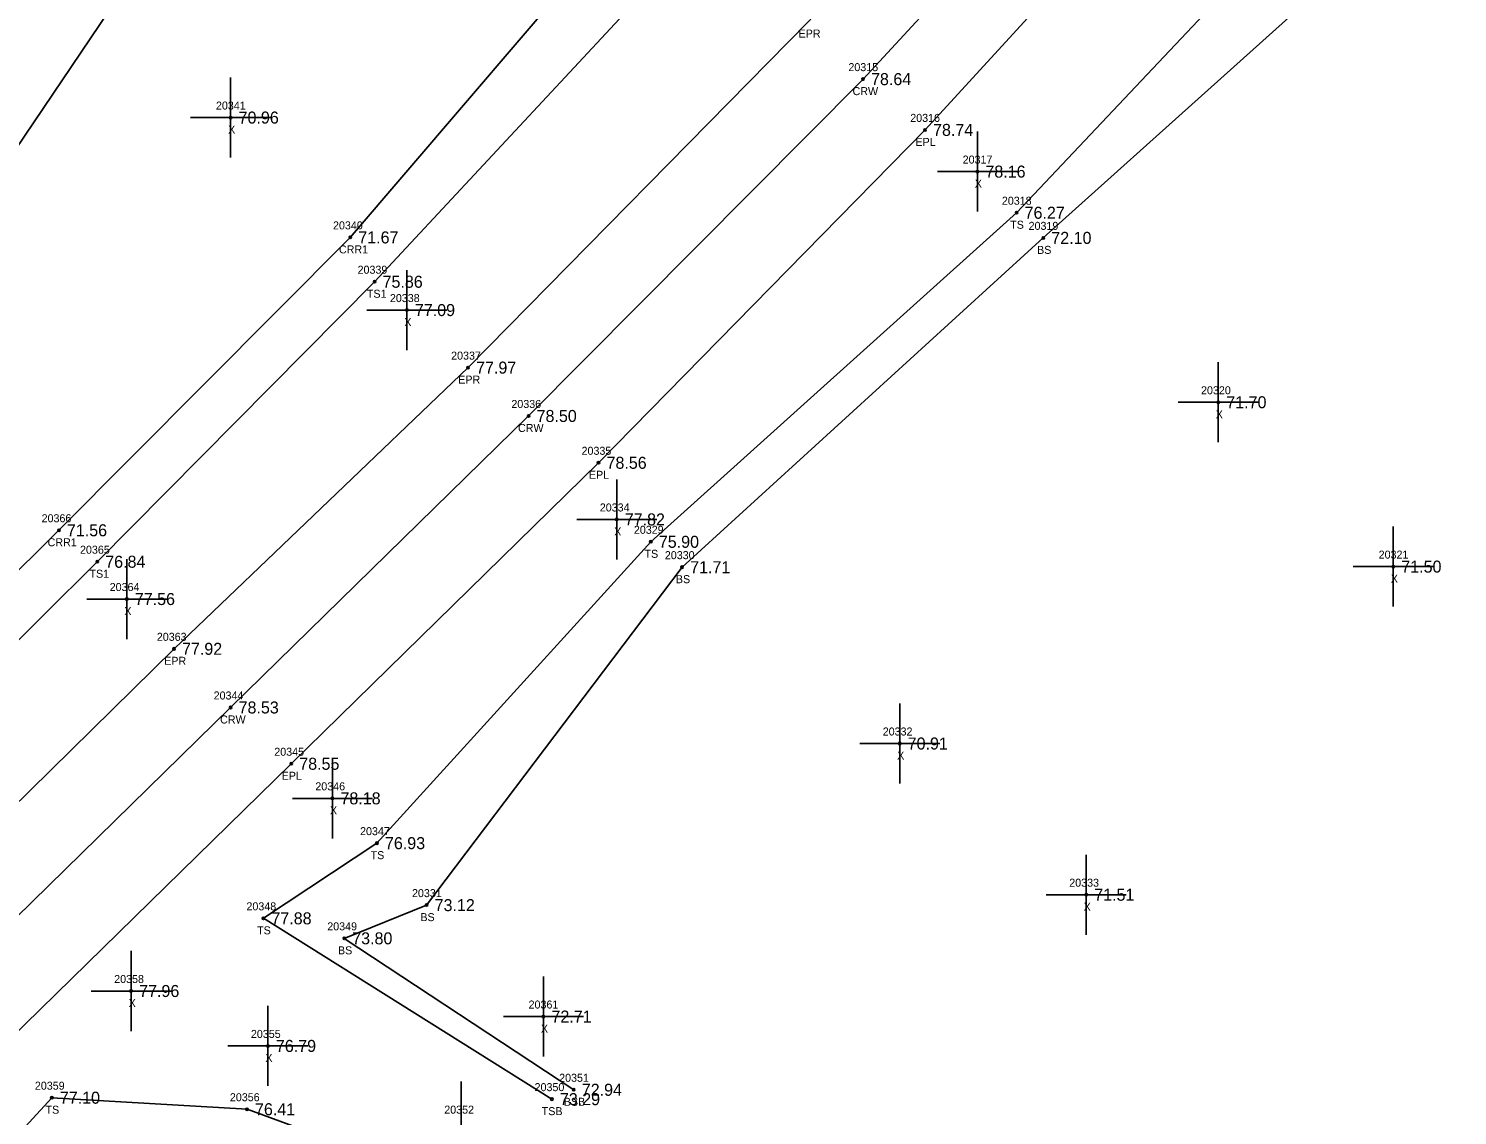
# Model space of a CAD drawing. Extents: x 2505300 to 2506184, y 912965 to 913825.
# Drawn here: x 2505552.8 to 2505731.4, y 913206.7 to 913342.5 of the extents above; entities that cross this region are included whole.
import ezdxf

# ---------------------------------------------------------------- set-up
doc = ezdxf.new("R2010")
doc.units = 0
for name, color, linetype in [('RD_DTM_BkLn1', 7, 'Continuous'), ('RD_DTM_BkLn2', 7, 'Continuous'), ('RD_DTM_BkLn_txCode', 7, 'Continuous'), ('RD_EX_H2O', 7, 'Continuous'), ('RD_EX_H2O_txCode', 7, 'Continuous'), ('RD_EX_Misc', 7, 'Continuous'), ('RD_EX_Misc_txCode', 7, 'Continuous'), ('RD_EX_Road', 7, 'Continuous'), ('RD_EX_Road_txCode', 7, 'Continuous'), ('RD_EX_TX_H2O_ELEV', 7, 'Continuous'), ('RD_EX_TX_Misc_ELEV', 7, 'Continuous'), ('RD_EX_TX_Road_ELEV', 7, 'Continuous'), ('RD_HC_Survey_ELEV', 7, 'Continuous'), ('RD_HC_Survey_txCode', 7, 'Continuous'), ('RD_SMD_Locator', 7, 'Continuous')]:
    doc.layers.add(name, color=color, linetype=linetype)

msp = doc.modelspace()

# ---------------------------------------------------------------- linework, layer by layer
at = {"layer": 'RD_DTM_BkLn1'}
msp.add_lwpolyline([(2505767.92, 913463.52), (2505733.49, 913421.6), (2505698.21, 913380.67), (2505657.08, 913336.16), (2505615.28, 913294.08), (2505578.04, 913257.66), (2505509.81, 913190.87), (2505437.56, 913120.73), (2505363.23, 913048.54)], dxfattribs=at)
at = {"layer": 'RD_DTM_BkLn2'}
for points in [[(2505753.71, 913473.94), (2505744.94, 913478.08), (2505723.86, 913460.1), (2505705.31, 913435.28), (2505675.97, 913399.31), (2505635.15, 913352.85), (2505596.03, 913310.85), (2505561.37, 913275.87), (2505492.57, 913207.56), (2505417.69, 913144.74), (2505344.31, 913068.67)], [(2505795.69, 913463.1), (2505792.51, 913445.22), (2505759.98, 913398.97), (2505723.99, 913356.17), (2505679.61, 913316.33), (2505634.47, 913275.19), (2505602.54, 913232.97), (2505592.24, 913228.82), (2505620.93, 913209.9)], [(2505778.84, 913452.68), (2505749.61, 913407.4), (2505717.38, 913363.03), (2505676.27, 913319.47), (2505630.56, 913278.36), (2505596.33, 913240.71), (2505582.14, 913231.32), (2505618.19, 913208.73)], [(2505608.57, 913197.02), (2505580.09, 913207.47), (2505555.7, 913208.91), (2505524.48, 913174.98), (2505452.19, 913104.88), (2505378.2, 913033.83)]]:
    msp.add_lwpolyline(points, dxfattribs=at)
at = {"layer": 'RD_EX_H2O'}
for points in [[(2505789.47, 913464.31), (2505758.18, 913486.1), (2505736.66, 913480.49), (2505719.32, 913463.86), (2505699.9, 913439.21), (2505669.03, 913402.75), (2505628.5, 913357.9), (2505593, 913316.39), (2505556.58, 913279.8), (2505487.72, 913211.38), (2505413.81, 913149.81), (2505341.31, 913072.1)], [(2505660.9, 913411.21), (2505598.96, 913382.03), (2505565.24, 913348.29), (2505539.28, 913309.84), (2505469.64, 913225.59)]]:
    msp.add_lwpolyline(points, dxfattribs=at)
at = {"layer": 'RD_EX_Misc'}
for p, q in [((2505578.04, 913326.36), (2505578.04, 913336.36)), ((2505573.04, 913331.36), (2505583.04, 913331.36)), ((2505671.37, 913319.61), (2505671.37, 913329.61)), ((2505666.37, 913324.61), (2505676.37, 913324.61)), ((2505600.07, 913302.31), (2505600.07, 913312.31)), ((2505595.07, 913307.31), (2505605.07, 913307.31)), ((2505701.48, 913290.79), (2505701.48, 913300.79)), ((2505696.48, 913295.79), (2505706.48, 913295.79)), ((2505626.3, 913276.15), (2505626.3, 913286.15)), ((2505621.3, 913281.15), (2505631.3, 913281.15)), ((2505723.35, 913270.26), (2505723.35, 913280.26)), ((2505565.07, 913266.21), (2505565.07, 913276.21)), ((2505718.35, 913275.26), (2505728.35, 913275.26)), ((2505560.07, 913271.21), (2505570.07, 913271.21)), ((2505661.66, 913248.16), (2505661.66, 913258.16)), ((2505656.66, 913253.16), (2505666.66, 913253.16)), ((2505590.77, 913241.31), (2505590.77, 913251.31)), ((2505585.77, 913246.31), (2505595.77, 913246.31)), ((2505684.97, 913229.27), (2505684.97, 913239.27)), ((2505679.97, 913234.27), (2505689.97, 913234.27)), ((2505565.61, 913217.24), (2505565.61, 913227.24)), ((2505617.14, 913214.05), (2505617.14, 913224.05)), ((2505560.61, 913222.24), (2505570.61, 913222.24)), ((2505582.7, 913210.38), (2505582.7, 913220.38)), ((2505612.14, 913219.05), (2505622.14, 913219.05)), ((2505577.7, 913215.38), (2505587.7, 913215.38)), ((2505606.85, 913200.92), (2505606.85, 913210.92))]:
    msp.add_line(p, q, dxfattribs=at)
at = {"layer": 'RD_EX_Road'}
for points in [[(2505758.23, 913470.96), (2505754.11, 913462.85), (2505725.4, 913427.85), (2505690.77, 913387.11), (2505650.25, 913343.36), (2505607.72, 913300.12), (2505570.97, 913264.99), (2505501.53, 913196.72), (2505431.76, 913128.83), (2505356.25, 913055.37)], [(2505777.56, 913455.88), (2505770.31, 913449.85), (2505741, 913414.45), (2505705.55, 913374.27), (2505664.83, 913329.82), (2505624.02, 913288.23), (2505585.62, 913250.63), (2505516.95, 913183.5), (2505444.27, 913113.56), (2505370.6, 913041.78)]]:
    msp.add_lwpolyline(points, dxfattribs=at)
at = {"layer": 'RD_SMD_Locator'}
for centre in [(2505657.08, 913336.16), (2505578.04, 913331.36), (2505664.83, 913329.82), (2505671.37, 913324.61), (2505676.27, 913319.47), (2505593, 913316.39), (2505679.61, 913316.33), (2505596.03, 913310.85), (2505600.07, 913307.31), (2505607.72, 913300.12), (2505701.48, 913295.79), (2505615.28, 913294.08), (2505624.02, 913288.23), (2505626.3, 913281.15), (2505556.58, 913279.8), (2505630.56, 913278.36), (2505561.37, 913275.87), (2505634.47, 913275.19), (2505723.35, 913275.26), (2505565.07, 913271.21), (2505570.97, 913264.99), (2505578.04, 913257.66), (2505661.66, 913253.16), (2505585.62, 913250.63), (2505590.77, 913246.31), (2505596.33, 913240.71), (2505602.54, 913232.97), (2505684.97, 913234.27), (2505582.14, 913231.32), (2505592.24, 913228.82), (2505565.61, 913222.24), (2505617.14, 913219.05), (2505582.7, 913215.38), (2505620.93, 913209.9), (2505555.7, 913208.91), (2505618.19, 913208.73), (2505580.09, 913207.47)]:
    msp.add_circle(centre, 0.15, dxfattribs=at)

# ---------------------------------------------------------------- texts
at = {"layer": 'RD_DTM_BkLn_txCode'}
for s, p in [('20318', (2505674.43, 913320.47)), ('TS', (2505675.47, 913317.47)), ('20319', (2505677.77, 913317.33)), ('BS', (2505678.83, 913314.33)), ('20339', (2505593.91, 913311.85)), ('TS1', (2505595.07, 913308.85)), ('20329', (2505628.44, 913279.36)), ('20365', (2505559.22, 913276.87)), ('TS', (2505629.77, 913276.36)), ('20330', (2505632.31, 913276.19)), ('TS1', (2505560.4, 913273.87)), ('BS', (2505633.69, 913273.19)), ('20347', (2505594.22, 913241.71)), ('TS', (2505595.54, 913238.71)), ('20331', (2505600.71, 913233.97)), ('20348', (2505580.02, 913232.32)), ('BS', (2505601.76, 913230.97)), ('TS', (2505581.35, 913229.32)), ('20349', (2505590.12, 913229.82)), ('BS', (2505591.46, 913226.82)), ('20351', (2505619.1, 913210.9)), ('20359', (2505553.58, 913209.91)), ('20350', (2505616.03, 913209.73)), ('20356', (2505577.95, 913208.47)), ('BSB', (2505619.68, 913207.9)), ('TS', (2505554.91, 913206.91)), ('TSB', (2505616.92, 913206.73))]:
    msp.add_text(s, height=1, dxfattribs=at).set_placement(p)
at = {"layer": 'RD_EX_H2O_txCode'}
for s, p in [('20340', (2505590.84, 913317.39)), ('CRR1', (2505591.58, 913314.39)), ('20366', (2505554.42, 913280.8)), ('CRR1', (2505555.17, 913277.8))]:
    msp.add_text(s, height=1, dxfattribs=at).set_placement(p)
at = {"layer": 'RD_EX_Misc_txCode'}
for s, p in [('20341', (2505576.21, 913332.36)), ('X', (2505577.73, 913329.36)), ('20317', (2505669.53, 913325.61)), ('X', (2505671.05, 913322.61)), ('20338', (2505597.95, 913308.31)), ('X', (2505599.75, 913305.31)), ('20320', (2505699.32, 913296.79)), ('X', (2505701.16, 913293.79)), ('20334', (2505624.18, 913282.15)), ('X', (2505625.98, 913279.15)), ('20321', (2505721.52, 913276.26)), ('X', (2505723.04, 913273.26)), ('20364', (2505562.93, 913272.21)), ('X', (2505564.76, 913269.21)), ('20332', (2505659.54, 913254.16)), ('X', (2505661.35, 913251.16)), ('20346', (2505588.63, 913247.31)), ('X', (2505590.46, 913244.31)), ('20333', (2505682.85, 913235.27)), ('X', (2505684.65, 913232.27)), ('20358', (2505563.49, 913223.24)), ('X', (2505565.3, 913220.24)), ('20361', (2505615.28, 913220.05)), ('20355', (2505580.58, 913216.38)), ('X', (2505616.82, 913217.05)), ('X', (2505582.38, 913213.38)), ('20352', (2505604.74, 913206.92))]:
    msp.add_text(s, height=1, dxfattribs=at).set_placement(p)
at = {"layer": 'RD_EX_Road_txCode'}
for s, p in [('EPR', (2505649.02, 913341.36)), ('20316', (2505662.98, 913330.82)), ('EPL', (2505663.63, 913327.82)), ('20337', (2505605.6, 913301.12)), ('EPR', (2505606.49, 913298.12)), ('20335', (2505621.9, 913289.23)), ('EPL', (2505622.82, 913286.23)), ('20363', (2505568.82, 913265.99)), ('EPR', (2505569.74, 913262.99)), ('20345', (2505583.5, 913251.63)), ('EPL', (2505584.42, 913248.63))]:
    msp.add_text(s, height=1, dxfattribs=at).set_placement(p)
at = {"layer": 'RD_EX_TX_H2O_ELEV'}
for s, p in [('71.67', (2505594, 913315.64)), ('71.56', (2505557.58, 913279.05))]:
    msp.add_text(s, height=1.5, dxfattribs=at).set_placement(p)
at = {"layer": 'RD_EX_TX_Misc_ELEV'}
for s, p in [('70.96', (2505579.04, 913330.61)), ('78.16', (2505672.37, 913323.86)), ('76.27', (2505677.27, 913318.72)), ('72.10', (2505680.61, 913315.58)), ('75.86', (2505597.03, 913310.1)), ('77.09', (2505601.07, 913306.56)), ('71.70', (2505702.48, 913295.04)), ('77.82', (2505627.3, 913280.4)), ('75.90', (2505631.56, 913277.61)), ('76.84', (2505562.37, 913275.12)), ('71.71', (2505635.47, 913274.44)), ('71.50', (2505724.35, 913274.51)), ('77.56', (2505566.07, 913270.46)), ('70.91', (2505662.66, 913252.41)), ('78.18', (2505591.77, 913245.56)), ('76.93', (2505597.33, 913239.96)), ('71.51', (2505685.97, 913233.52)), ('73.12', (2505603.54, 913232.22)), ('77.88', (2505583.14, 913230.57)), ('73.80', (2505593.24, 913228.07)), ('77.96', (2505566.61, 913221.49)), ('72.71', (2505618.14, 913218.3)), ('76.79', (2505583.7, 913214.63)), ('72.94', (2505621.93, 913209.15)), ('77.10', (2505556.7, 913208.16)), ('76.41', (2505581.09, 913206.72)), ('73.29', (2505619.19, 913207.98))]:
    msp.add_text(s, height=1.5, dxfattribs=at).set_placement(p)
at = {"layer": 'RD_EX_TX_Road_ELEV'}
for s, p in [('78.74', (2505665.83, 913329.07)), ('77.97', (2505608.72, 913299.37)), ('78.56', (2505625.02, 913287.48)), ('77.92', (2505571.97, 913264.24)), ('78.55', (2505586.62, 913249.88))]:
    msp.add_text(s, height=1.5, dxfattribs=at).set_placement(p)
at = {"layer": 'RD_HC_Survey_ELEV'}
for s, p in [('78.64', (2505658.08, 913335.41)), ('78.50', (2505616.28, 913293.33)), ('78.53', (2505579.04, 913256.91))]:
    msp.add_text(s, height=1.5, dxfattribs=at).set_placement(p)
at = {"layer": 'RD_HC_Survey_txCode'}
for s, p in [('20315', (2505655.25, 913337.16)), ('CRW', (2505655.77, 913334.16)), ('20336', (2505613.13, 913295.08)), ('CRW', (2505613.96, 913292.08)), ('20344', (2505575.92, 913258.66)), ('CRW', (2505576.73, 913255.66))]:
    msp.add_text(s, height=1, dxfattribs=at).set_placement(p)

doc.saveas('drawing.dxf')
